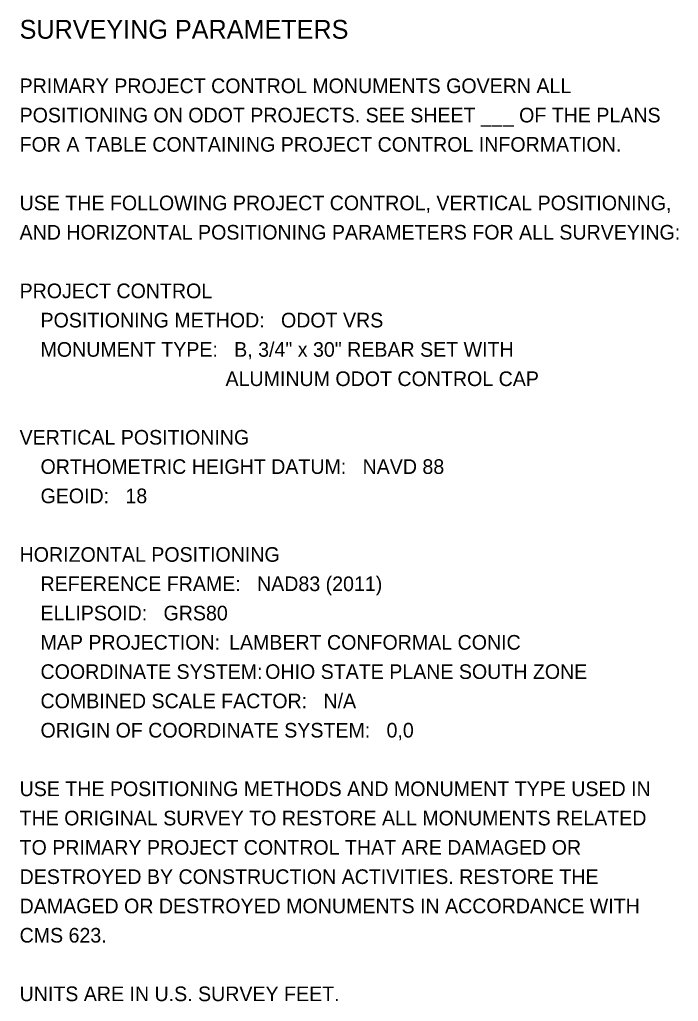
# Model space of a CAD drawing. Extents: x -30 to 80, y -20 to 49.
# Drawn here: x -29.61 to -23.31, y 11.55 to 20.93 of the extents above; entities that cross this region are included whole.
import ezdxf

# ---------------------------------------------------------------- set-up
doc = ezdxf.new("R2010")
doc.units = 0
doc.layers.add('SH_Text', color=7, linetype='Continuous')

msp = doc.modelspace()

# ---------------------------------------------------------------- texts
at = {"layer": 'SH_Text'}
for s, height, p in [('SURVEYING PARAMETERS', 0.18, (-29.6087, 20.7499)), ('PRIMARY PROJECT CONTROL MONUMENTS GOVERN ALL', 0.14, (-29.6087, 20.2299)), ('POSITIONING ON ODOT PROJECTS. SEE SHEET ___ OF THE PLANS', 0.14, (-29.6087, 19.9499)), ('FOR A TABLE CONTAINING PROJECT CONTROL INFORMATION.', 0.14, (-29.6087, 19.6699)), ('USE THE FOLLOWING PROJECT CONTROL, VERTICAL POSITIONING,', 0.14, (-29.6087, 19.1099)), ('AND HORIZONTAL POSITIONING PARAMETERS FOR ALL SURVEYING:', 0.14, (-29.6087, 18.8299)), ('PROJECT CONTROL', 0.14, (-29.6087, 18.2699)), ('POSITIONING METHOD:   ODOT VRS', 0.14, (-29.4087, 17.9899)), ('MONUMENT TYPE:   B, 3/4" x 30" REBAR SET WITH', 0.14, (-29.4087, 17.7099)), ('                                  ALUMINUM ODOT CONTROL CAP', 0.14, (-29.4087, 17.4299)), ('VERTICAL POSITIONING', 0.14, (-29.6087, 16.8699)), ('ORTHOMETRIC HEIGHT DATUM:   NAVD 88', 0.14, (-29.4087, 16.5899)), ('GEOID:   18', 0.14, (-29.4087, 16.3099)), ('HORIZONTAL POSITIONING', 0.14, (-29.6087, 15.7499)), ('REFERENCE FRAME:   NAD83 (2011)', 0.14, (-29.4087, 15.4699)), ('ELLIPSOID:   GRS80', 0.14, (-29.4087, 15.1899)), ('MAP PROJECTION:   ', 0.14, (-29.4087, 14.9099)), ('LAMBERT CONFORMAL CONIC', 0.14, (-27.6064, 14.9099)), ('COORDINATE SYSTEM: ', 0.14, (-29.4087, 14.6299)), ('  OHIO STATE PLANE SOUTH ZONE', 0.14, (-27.3653, 14.6299)), ('COMBINED SCALE FACTOR:   N/A', 0.14, (-29.4087, 14.3499)), ('ORIGIN OF COORDINATE SYSTEM:   0,0', 0.14, (-29.4087, 14.0699)), ('USE THE POSITIONING METHODS AND MONUMENT TYPE USED IN', 0.14, (-29.6087, 13.5099)), ('THE ORIGINAL SURVEY TO RESTORE ALL MONUMENTS RELATED', 0.14, (-29.6087, 13.2299)), ('TO PRIMARY PROJECT CONTROL THAT ARE DAMAGED OR', 0.14, (-29.6087, 12.9499)), ('DESTROYED BY CONSTRUCTION ACTIVITIES. RESTORE THE', 0.14, (-29.6087, 12.6699)), ('DAMAGED OR DESTROYED MONUMENTS IN ACCORDANCE WITH', 0.14, (-29.6087, 12.3899)), ('CMS 623.', 0.14, (-29.6087, 12.1099)), ('UNITS ARE IN U.S. SURVEY FEET.', 0.14, (-29.6087, 11.5499))]:
    msp.add_text(s, height=height, dxfattribs=at).set_placement(p)

doc.saveas('drawing.dxf')
